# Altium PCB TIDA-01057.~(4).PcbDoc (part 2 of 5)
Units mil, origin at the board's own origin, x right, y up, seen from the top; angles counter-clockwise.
Board outline 4448 x 3930 mil, 4 copper layers (Layer 1 - Top Layer, Layer 2 - GND, Layer 3 - PWR, Layer 4 - Bottom Layer), stack 59.034 mil thick; 537 components, 284 nets, 1540 pads, 770 vias.
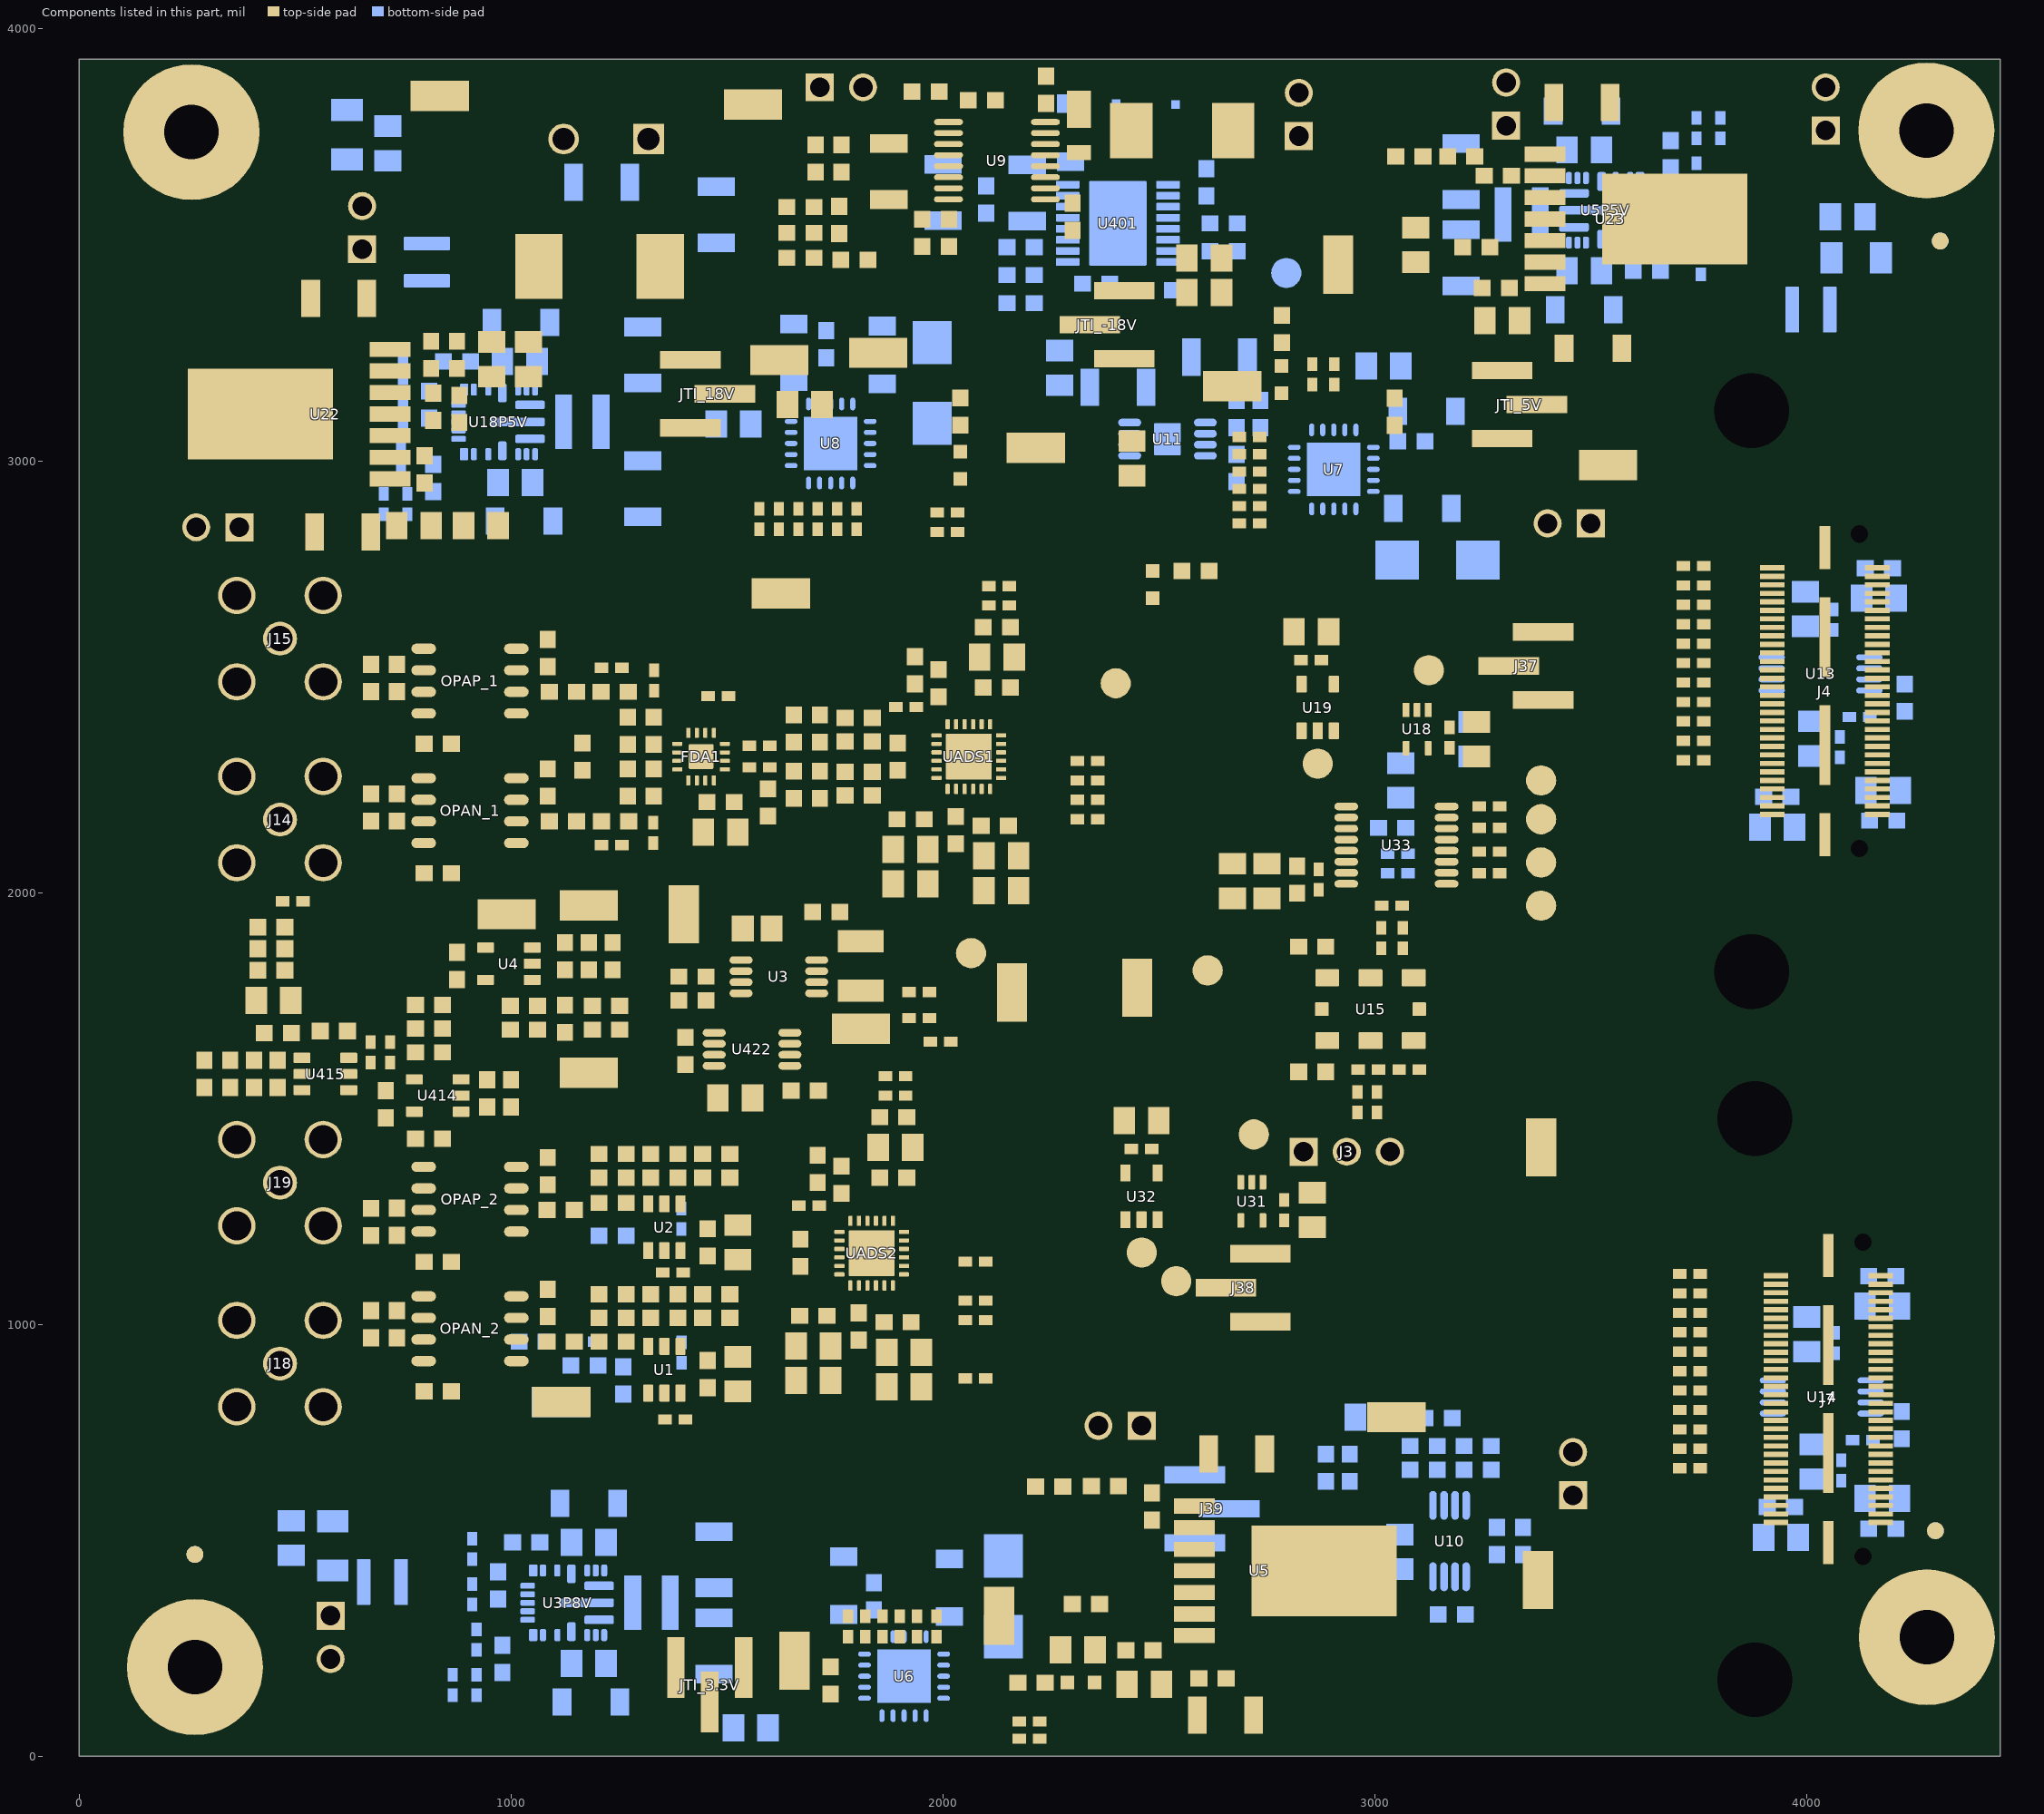
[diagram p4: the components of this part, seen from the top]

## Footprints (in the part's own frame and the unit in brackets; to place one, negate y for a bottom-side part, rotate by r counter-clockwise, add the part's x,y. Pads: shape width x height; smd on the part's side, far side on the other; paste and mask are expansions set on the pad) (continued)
DGK0008A_N [mm] "TSOP, 8-Leads, Body 3x3mm, Pitch 0.65mm, IPC Medium Density"
  oval 1.35x0.45 smd: 1(-2.225,0.975) 2(-2.225,0.325) 3(-2.225,-0.325) 4(-2.225,-0.975) 5(2.225,-0.975) 6(2.225,-0.325) 7(2.225,0.325) 8(2.225,0.975)
  silkscreen extent -2.75,-1.55 0.95,1.55, body extent -2.45,-1.5 2.45,1.5, height 0.96
DGN0008D_N [mm] "TSOP, 8-Leads, Body 3x3mm, Pitch 0.65mm, Thermal Pad 1.89x1.57mm, IPC Medium Density"
  rrect100% 1.35x0.45 smd: 1(-2.225,0.975) 2(-2.225,0.325) 3(-2.225,-0.325) 4(-2.225,-0.975) 5(2.225,-0.975) 6(2.225,-0.325) 7(2.225,0.325) 8(2.225,0.975)
  rrect6% 1.57x1.89 smd: 9(0,0)
  silkscreen extent -2.73,-1.55 0.95,1.55, body extent -2.46,-1.5 2.46,1.5, height 1.1
DR73 [mm]
  rect 2.5x3.25 smd: 1(-3,0) 2(3,0)
  silkscreen extent -4.75,-3.8 4.75,3.8, body extent -3.8,-3.8 3.8,3.8, height 3.55
Fiducial10-20 [mm]
  round 1 smd mask+0.5: 1(0,0)
Keystone_1902C [mil] "Hex Standoff, 4-40 threaded, nylon"
  body extent -145,-126 146,126, height 501
MTC16_N [mm] "TSOP, 16-Leads, Body 5x4.4mm, Pitch 0.65mm, IPC Medium Density"
  oval 1.7x0.35 smd: 1(-2.85,2.275) 2(-2.85,1.625) 3(-2.85,0.975) 4(-2.85,0.325) 5(-2.85,-0.325) 6(-2.85,-0.975) 7(-2.85,-1.625) 8(-2.85,-2.275) 9(2.85,-2.275) 10(2.85,-1.625) 11(2.85,-0.975) 12(2.85,-0.325) 13(2.85,0.325) 14(2.85,0.975) 15(2.85,1.625) 16(2.85,2.275)
  silkscreen extent -2.97,-2.55 1.6,3.12, body extent -2.25,-2.55 2.25,2.55, height 1.1
MUA08A_N [mm] "TSOP, 8-Leads, Body 3x3mm, Pitch 0.65mm, IPC Medium Density"
  oval 1.7x0.45 smd: 1(-2.1,0.975) 2(-2.1,0.325) 3(-2.1,-0.325) 4(-2.1,-0.975) 5(2.1,-0.975) 6(2.1,-0.325) 7(2.1,0.325) 8(2.1,0.975)
  silkscreen extent -2.22,-1.55 0.85,1.88, body extent -1.6,-1.6 1.6,1.6, height 1.09
Net-Tie_50milWide_30milLong [mil] "50mil net tie, no solder mask opening, no solder paste"
  rect 30x100 on Mid1 paste-20 mask-20: 1(-15,0) 2(15,0)
NR3015 [mm] "SMD, 2-Leads, Body 3x3mm"
  rrect12% 0.8x2.7 smd: 1(-1.1,0) 2(1.1,0)
  silkscreen extent -0.3,-1.6 0.3,1.6, body extent -1.5,-1.5 1.5,1.5, height 1.5
"NY PMS 440 0025 PH" [mm] "4-40 nylon screw and mounting hole"
  round 8 hole 3.2: 1(0,0)
  body extent -3.3,-3.3 3.3,3.3, height 2.69
Pb-Free_Overlay_Small [mil]
  silkscreen extent -46,-46 46,46
PogoPad [mil] "No Solder Paste"
  round 70 smd paste-35: 1(0,0)
PowerDI123 [mm] "Diodes Inc recommended land pattern, document number DS30628 Rev. 6-2"
  rect 2.2x1.4 smd: 1(-1.275,0)
  rect 0.9x1.4 smd: 2(1.275,0)
  silkscreen extent -3.1,-1.09 1.76,1.09, body extent -2.38,-0.97 1.52,0.96, height 1
PW0016A_N [mm] "TSOP, 16-Leads, Body 5x4.4mm, Pitch 0.65mm, IPC Medium Density"
  oval 1.4x0.45 smd: 1(-2.95,2.275) 2(-2.95,1.625) 3(-2.95,0.975) 4(-2.95,0.325) 5(-2.95,-0.325) 6(-2.95,-0.975) 7(-2.95,-1.625) 8(-2.95,-2.275) 9(2.95,-2.275) 10(2.95,-1.625) 11(2.95,-0.975) 12(2.95,-0.325) 13(2.95,0.325) 14(2.95,0.975) 15(2.95,1.625) 16(2.95,2.275)
  silkscreen extent -3.5,-2.55 1.85,2.75, body extent -3.21,-2.5 3.21,2.5, height 1
PWP0016G_N [mm] "TSOP, 16-Leads, Body 5x4.4mm, Pitch 0.65mm, Thermal Pad 2.41x3.29 mm, IPC Medium Density"
  rrect22% 1.4x0.45 smd: 1(-2.95,2.275) 2(-2.95,1.625) 3(-2.95,0.975) 4(-2.95,0.325) 5(-2.95,-0.325) 6(-2.95,-0.975) 7(-2.95,-1.625) 8(-2.95,-2.275) 9(2.95,-2.275) 10(2.95,-1.625) 11(2.95,-0.975) 12(2.95,-0.325) 13(2.95,0.325) 14(2.95,0.975) 15(2.95,1.625) 16(2.95,2.275)
  rrect6% 3.4x5 smd paste-1.7 mask-1.7: 17(0,0)
  rrect4% 2.41x3.29 on Bottom Paste: 17(0,0)
  rrect4% 2.41x3.29 on Bottom Solder: 17(0,0)
  silkscreen extent -3.5,-2.55 1.5,2.73, body extent -3.21,-2.5 3.21,2.5, height 0.99
RGE0024H [mm] "QFN, 24-Leads, Body 4x4mm, Pitch 0.5mm, Thermal Pad 2.7x2.7mm, TI Recommended"
  rrect40% 0.6x0.25 smd: 1(-1.9,1.25) 2(-1.9,0.75) 3(-1.9,0.25) 4(-1.9,-0.25) 5(-1.9,-0.75) 6(-1.9,-1.25) 13(1.9,-1.25) 14(1.9,-0.75) 15(1.9,-0.25) 16(1.9,0.25) 17(1.9,0.75) 18(1.9,1.25)
  rrect40% 0.25x0.6 smd: 7(-1.25,-1.9) 8(-0.75,-1.9) 9(-0.25,-1.9) 10(0.25,-1.9) 11(0.75,-1.9) 12(1.25,-1.9) 19(1.25,1.9) 20(0.75,1.9) 21(0.25,1.9) 22(-0.25,1.9) 23(-0.75,1.9) 24(-1.25,1.9)
  rrect4% 2.7x2.7 smd paste-1.35: 25(0,0)
  silkscreen extent -2.22,-2.22 2.22,2.22, body extent -2.07,-2.07 2.07,2.07, height 1.01
RGT0016A [mm] "QFN, 16-Leads, Body 3x3mm, Pitch 0.5mm, Thermal Pad 1.45x1.45mm, TI Recommended"
  rrect42% 0.6x0.24 smd: 1(-1.4,0.75) 2(-1.4,0.25) 3(-1.4,-0.25) 4(-1.4,-0.75) 9(1.4,-0.75) 10(1.4,-0.25) 11(1.4,0.25) 12(1.4,0.75)
  rrect42% 0.24x0.6 smd: 5(-0.75,-1.4) 6(-0.25,-1.4) 7(0.25,-1.4) 8(0.75,-1.4) 13(0.75,1.4) 14(0.25,1.4) 15(-0.25,1.4) 16(-0.75,1.4)
  rrect7% 1.45x1.45 smd paste-0.725: 17(0,0)
  silkscreen extent -1.72,-1.73 1.72,1.73, body extent -1.57,-1.57 1.58,1.58, height 1.01
RGW0020A [mm] "QFN, 20-Leads, Body 5x5mm, Pitch 0.65mm, Thermal Pad 3.15x3.15mm, TI Recommended"
  oval 0.75x0.3 smd: 1(-2.325,1.3) 2(-2.325,0.65) 3(-2.325,0) 4(-2.325,-0.65) 5(-2.325,-1.3) 11(2.325,-1.3) 12(2.325,-0.65) 13(2.325,0) 14(2.325,0.65) 15(2.325,1.3)
  oval 0.3x0.75 smd: 6(-1.3,-2.325) 7(-0.65,-2.325) 8(0,-2.325) 9(0.65,-2.325) 10(1.3,-2.325) 16(1.3,2.325) 17(0.65,2.325) 18(0,2.325) 19(-0.65,2.325) 20(-1.3,2.325)
  rect 3.15x3.15 smd paste-1.575: 21(0,0)
  silkscreen extent -2.73,-2.73 2.73,2.73, body extent -2.58,-2.57 2.57,2.58, height 1.01
RNL0022A_NV [mm] "VQFN, 22 pin, 0.5 mm pitch"
  rrect25% 0.7x0.5 smd paste-0.05 mask-0.05: 1(-1.9,2) 17(1.9,2)
  rrect40% 0.7x0.35 smd paste-0.05 mask-0.05: 2(-1.9,1.425) 3(-1.9,0.575) 15(1.9,0.575) 16(1.9,1.425)
  rrect40% 1.1x0.5 smd paste-0.25 mask-0.05: 4(-1.7,-0.25) 14(1.7,-0.25)
  rrect25% 0.4x0.4 on Bottom Paste: 4A(-2,-0.25) 4B(-1.4,-0.25) 14A(1.4,-0.25) 14B(2,-0.25)
  rrect57% 0.7x0.35 smd paste-0.05 mask-0.05: 5(-1.9,-1.175) 6(-1.9,-1.675) 7(-1.9,-2.175) 11(1.9,-2.175) 12(1.9,-1.675) 13(1.9,-1.175)
  rrect40% 0.5x1.74 smd paste-0.25 mask-0.05: 8(-1,-1.875) 10(1,-1.875)
  rrect25% 0.4x0.66 on Bottom Paste: 8A(-1,-1.445) 8B(-1,-2.305) 10A(1,-1.445) 10B(1,-2.305)
  rrect40% 0.5x3.25 smd paste-0.25 mask-0.05: 9(0,-1.125)
  rrect25% 0.4x0.63 on Bottom Paste: 9A(0,0.12) 9B(0,-0.71) 9C(0,-1.54) 9D(0,-2.37)
  rrect40% 0.35x0.85 smd paste-0.05 mask-0.05: 18(1,2.325) 19(0.5,2.325) 20(0,2.325) 21(-0.5,2.325) 22(-1,2.325)
  silkscreen extent -2.15,-2.65 2.15,2.65, body extent -2,-2.5 2,2.5, height 0.9
Samtec_QTH-030-01-x-D-A [mil] "Header (Shrouded), 19.7mil, 30x2, SMT"
  rect 12x57 smd mask+1: 1(-285.7,121.5) 2(-285.7,-121.5) 3(-266,121.5) 4(-266,-121.5) 5(-246.3,121.5) 6(-246.3,-121.5) 7(-226.6,121.5) 8(-226.6,-121.5) 9(-206.9,121.5) 10(-206.9,-121.5) 11(-187.2,121.5) 12(-187.2,-121.5) 13(-167.5,121.5) 14(-167.5,-121.5) 15(-147.8,121.5) 16(-147.8,-121.5) 17(-128.1,121.5) 18(-128.1,-121.5) 19(-108.4,121.5) 20(-108.4,-121.5) 21(-88.7,121.5) 22(-88.7,-121.5) 23(-69,121.5) 24(-69,-121.5) 25(-49.3,121.5) 26(-49.3,-121.5) 27(-29.6,121.5) 28(-29.6,-121.5) 29(-9.9,121.5) 30(-9.9,-121.5) 31(9.8,121.5) 32(9.8,-121.5) 33(29.5,121.5) 34(29.5,-121.5) 35(49.2,121.5) 36(49.2,-121.5) 37(68.9,121.5) 38(68.9,-121.5) 39(88.6,121.5) 40(88.6,-121.5) 41(108.3,121.5) 42(108.3,-121.5) 43(128,121.5) 44(128,-121.5) 45(147.7,121.5) 46(147.7,-121.5) 47(167.4,121.5) 48(167.4,-121.5) 49(187.1,121.5) 50(187.1,-121.5) 51(206.8,121.5) 52(206.8,-121.5) 53(226.5,121.5) 54(226.5,-121.5) 55(246.2,121.5) 56(246.2,-121.5) 57(265.9,121.5) 58(265.9,-121.5) 59(285.6,121.5) 60(285.6,-121.5)
  round 0 hole 40 unplated mask+1: MH1(-364,80) MH2(364,80)
  rect 100x25 smd mask+1: MP1(-332.7,0) MP4(332.3,0)
  rect 185x25 smd mask+1: MP2(-125.2,0) MP3(124.8,0)
  silkscreen extent -394,-118 394,131, body extent -394,-140 394,140, height 170
Samtec_TMM-103-01-x-S-SM [mm] "Header,2mm, 3x1, SMT"
  rect 1.02x3.56 smd: 1(-2,1.015) 2(0,-1.015) 3(2,1.015)
  silkscreen extent -3.2,-0.99 3,0.99, body extent -3,-2.41 3,2.41, height 5.97
SIA0008B [mm] "SIP 8-Leads, Body 5x7mm"
  rrect17% 1x0.6 on Top Paste: 1(-1.85,2.14) 1(-1.85,2.94) 2(-1.85,-0.4) 2(-1.85,0.4) 3(-1.85,-2.94) 3(-1.85,-2.14) 4(1.85,-2.94) 4(1.85,-2.14) 5(1.85,-0.4) 5(1.85,0.4) 6(1.85,2.14) 6(1.85,2.94)
  rrect10% 1x1.4 smd paste-0.5: 1(-1.85,2.54) 2(-1.85,0) 3(-1.85,-2.54) 4(1.85,-2.54) 5(1.85,0) 6(1.85,2.54)
  rrect12% 0.8x0.8 smd: 7(0,2.865) 8(0,-2.865)
  silkscreen extent -2.64,-3.63 2.64,3.63, body extent -2.56,-3.56 2.56,3.56, height 1.13
SMC [mil] "Molded Diode, 2-Leads, Body 6.9x5.8mm, IPC Medium Density, based on OnSemi component dimensions and land patterns"
  rect 110x150 smd: 1(-140.49,0) 2(140.49,0)
  silkscreen extent -221,-124 189,123, body extent -156,-116 156,116, height 91
Testpoint_Keystone_Miniature [mil] "Miniature SMT test point"
  rect 135x70 smd: 1(0,0)
  silkscreen extent -78,-46 78,45, body extent -52,-20 52,20, height 61
TI_Stacked_Overlay_Small [mil]
  silkscreen extent -418,-98 418,98
TSOP65P640X120-8N [mm] "TSOP, 8-Leads, Body 3.1x4.5mm (max), Pitch 0.65mm, IPC Medium Density"
  oval 1.55x0.35 smd mask+0.08: 1(-2.875,0.975) 2(-2.875,0.325) 3(-2.875,-0.325) 4(-2.875,-0.975) 5(2.875,-0.975) 6(2.875,-0.325) 7(2.875,0.325) 8(2.875,0.975)
  silkscreen extent -1.7,-1.55 1.7,1.55, body extent -2.25,-1.55 2.25,1.55, height 1.21
TZA07A_V [mm] "D2-PAK, 8-Leads, Body 9.9x10.2mm, Pitch 1.27mm, Lead Span 13.8mm, NSC Recommended"
  rect 2.41x0.89 smd: 1(-5.35,3.81) 2(-5.35,2.54) 3(-5.35,1.27) 4(-5.35,0) 5(-5.35,-1.27) 6(-5.35,-2.54) 7(-5.35,-3.81)
  rect 8.54x5.35 smd: 8(2.28,0)
  silkscreen extent -5.47,-5.15 -2.7,5.15, body extent -2.55,-5.2 7.55,5.2, height 4.67
WE-TPC_2828 [mm] "WURTH"
  rect 1x3.2 smd: 1(-1.1,0) 2(1.1,0)
  body extent -1.5,-1.5 1.5,1.5, height 3
WE-TPC_3816 [mm] "WERTH"
  rect 0.5x0.5 smd: 1(-1.75,0) 2(1.75,0.05)
  Layer 1 - Top Layer region: 0.55,2.15 2.15,2.15 2.15,-2.15 0.55,-2.15 0.55,-1.35 0.56,-1.173 1.015,-0.813 1.267,-0.29 1.267,0.29 1.015,0.813 0.56,1.173 0.56,1.173 0.55,1.4
  Layer 1 - Top Layer region: -0.55,-2.15 -2.15,-2.15 -2.15,2.15 -0.55,2.15 -0.55,1.35 -0.56,1.173 -1.015,0.813 -1.267,0.29 -1.267,-0.29 -1.015,-0.813 -0.56,-1.173 -0.56,-1.173 -0.55,-1.4
  silkscreen extent -0.3,-2.15 0.3,2.15, body extent -2.05,-2.05 2.05,2.05, height 1.8
WL-SMCW_RED [mm] "WURTH"
  rect 0.8x0.8 smd: 1(-0.8,0) 2(0.8,0)
  silkscreen extent -1.9,-0.8 1.2,0.8, body extent -0.85,-0.45 0.85,0.45, height 0.8
WURTH_61300211121 [mm] "Header, 2.54mm, 2x1, TH"
  rect 1.65x1.65 hole 1.15: 1(-1.27,0)
  round 1.65 hole 1.15: 2(1.27,0)
  silkscreen extent -2.54,-1.27 2.54,1.6, body extent -2.54,-1.27 2.54,1.27, height 8.54
WURTH_61300311121 [mm] "Header, 2.54mm, 3x1, TH"
  rect 1.65x1.65 hole 1.15: 1(-2.54,0)
  round 1.65 hole 1.15: 2(0,0) 3(2.54,0)
  silkscreen extent -3.81,-1.27 3.81,1.6, body extent -3.81,-1.27 3.81,1.27, height 8.54
Wurth_691213710002 [mm] "TH, 2-Leads, Body 10x8.3mm, Pitch 5mm"
  rect 1.8x1.8 hole 1.3: 1(-2.5,0)
  round 1.8 hole 1.3: 2(2.5,0)
  silkscreen extent -5,-4.75 5,4.15, body extent -5.6,-4.15 5,4.15, height 10
Wurth_WA-SMSI [mm] "ROUND STANDOFF M3 STEEL 5MM"
  round 0 hole 4.4 unplated: ""(0,0)
  Layer 1 - Top Layer region: -3.711,0 -3.666,-0.581 -3.53,-1.147 -3.307,-1.685 -3.003,-2.182 -2.624,-2.624 -2.182,-3.003 -1.685,-3.307 -1.147,-3.53 -0.581,-3.666 0,-3.711 0.581,-3.666 1.147,-3.53 1.685,-3.307 2.182,-3.003 2.624,-2.624 3.003,-2.182 3.307,-1.685 3.53,-1.147 3.666,-0.581 3.711,0 3.7,0 2.466,0 2.418,-0.481 2.278,-0.944 2.05,-1.37 1.744,-1.744 1.37,-2.05 0.944,-2.278 0.481,-2.418 0,-2.466 -0.481,-2.418 -0.944,-2.278 -1.37,-2.05 -1.744,-1.744 -2.05,-1.37 -2.278,-0.944 -2.418,-0.481 -2.466,0 -2.454,0
  Layer 1 - Top Layer region: -3.711,0 -3.666,0.581 -3.53,1.147 -3.307,1.685 -3.003,2.182 -2.624,2.624 -2.182,3.003 -1.685,3.307 -1.147,3.53 -0.581,3.666 0,3.711 0.581,3.666 1.147,3.53 1.685,3.307 2.182,3.003 2.624,2.624 3.003,2.182 3.307,1.685 3.53,1.147 3.666,0.581 3.711,0 3.7,0 2.466,0 2.418,0.481 2.278,0.944 2.05,1.37 1.744,1.744 1.37,2.05 0.944,2.278 0.481,2.418 0,2.466 -0.481,2.418 -0.944,2.278 -1.37,2.05 -1.744,1.744 -2.05,1.37 -2.278,0.944 -2.418,0.481 -2.466,0 -2.454,0
  silkscreen extent -4.1,-4.1 4.1,4.1, body extent -3,-3 3,3, height 5

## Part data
24Vin GNDin TP3 TP8 TP25 TP26 TP27 TP28 TP29 TP30 TP_3P3V TP_3P8V TP_5P5V TP_18P5V TPAGND1 TPAGND2 TPAGND3 TPAGND4 TPGND1 TPGND2 TPGND3 TPGND4 TPV4: "Test Point, Miniature, SMT", Manufacturer=Keystone, Supplier Part Number 1=36-5015TR-ND
C1 C43 C47 C354 C389 C391 C408 Cin Cin1 Cin2 Cin3 Cout2: "CAP, CERM, 10 兪F, 50 V, +/- 10%, X7R, 1210", Cap_Case=1210, Manufacturer="Taiyo Yuden", Supplier Part Number 1=587-3167-1-ND, TempCo=X7R, Tolerance_%=10, Value1=Unknown, Value2=50V, ValueDisplayed=10兪F
C3: "CAP, CERM, 10uF, 10V, +/-10%, X7R, 0805", Cap_Case=0805, Manufacturer=MuRata, Supplier Part Number 1=490-3905-1-ND, TempCo=X7R, Tolerance_%=10, Value1="0.003 ohm", Value2=10V, ValueDisplayed=10兪F
C4: "CAP, CERM, 1uF, 10V, +/-10%, X7R, 0603", Cap_Case=0603, Manufacturer=MuRata, Supplier Part Number 1=490-3899-1-ND, TempCo=X7R, Tolerance_%=10, Value1="0.011 ohm", Value2=10V, ValueDisplayed=1兪F
C5: "CAP, CERM, 47 兪F, 10 V, +/- 10%, X7R, 1210", Cap_Case=1210, Manufacturer=MuRata, Supplier Part Number 1=490-5312-1-ND, TempCo=X7R, Tolerance_%=10, Value1=Unknown, Value2=10V, ValueDisplayed=47兪F
C9 C12 C13 C16 C17 C20 Cout4: "CAP, CERM, 47 兪F, 25 V, +/- 20%, X5R, 1206_190", Cap_Case=1206, Manufacturer=TDK, Supplier Part Number 1=445-8047-1-ND, TempCo=X5R, Tolerance_%=20, Value1=Unknown, Value2=25V, ValueDisplayed=47兪F
C10: "CAP, CERM, 1000 pF, 100 V, +/- 10%, X7R, AEC-Q200 Grade 1, 0603", Cap_Case=0603, Manufacturer=TDK, Supplier Part Number 1=445-5806-1-ND, TempCo=X7R, Tolerance_%=10, Value1="1.97137 ohm", Value2=100V, ValueDisplayed=1000pF
C11 C42 C45 Cout3: "CAP, CERM, 1 兪F, 100 V, +/- 10%, X7S, 0805", Cap_Case=0805, Manufacturer=TDK, Supplier Part Number 1=445-5205-1-ND, TempCo=X7S, Tolerance_%=10, Value1="0.008255 ohm", Value2=100V, ValueDisplayed=1兪F
C14 C18: "CAP, CERM, 1000 pF, 50 V, +/- 1%, C0G/NP0, 0603", Cap_Case=0603, Manufacturer=MuRata, Supplier Part Number 1=490-6377-1-ND, TempCo=C0G/NP0, Tolerance_%=1, Value1=Unknown, Value2=50V, ValueDisplayed=1000pF
C15 C19 C318 C319 C321 C339 C348 C453 CR479: "CAP, CERM, 1 兪F, 25 V, +/- 10%, X7R, 0603", Cap_Case=0603, Manufacturer=MuRata, Supplier Part Number 1=490-5307-1-ND, TempCo=X7R, Tolerance_%=10, Value1=Unknown, Value2=25V, ValueDisplayed=1兪F
C21 C22 C57 C58 C59 C60 C261 C262 C271 C272 C284 C287 C288 C289 C290 C291 C304 C305 C306 C307 C308 C338 C343 C345 C347 CR481: "CAP, CERM, 10 兪F, 10 V, +/- 10%, X7R, 0805", Cap_Case=0805, Manufacturer=MuRata, Supplier Part Number 1=490-3905-1-ND, TempCo=X7R, Tolerance_%=10, Value1="0.003 ohm", Value2=10V, ValueDisplayed=10兪F
C23 C24 C33: "CAP, CERM, 10 兪F, 10 V, +/- 20%, X5R, 0603", Cap_Case=0603, Manufacturer=MuRata, TempCo=X5R, Tolerance_%=20, Value1=Unknown, Value2=10V, ValueDisplayed=10兪F
C25: "CAP, CERM, 0.47 兪F, 25 V, +/- 10%, X7R, 0603", Cap_Case=0603, Manufacturer=MuRata, Supplier Part Number 1=490-3291-1-ND, TempCo=X7R, Tolerance_%=10, Value1=Unknown, Value2=25V, ValueDisplayed=0.47兪F
C26 C28: "CAP, CERM, 22 兪F, 6.3 V, +/- 20%, X5R, 0603", Cap_Case=0603, Manufacturer=MuRata, Supplier Part Number 1=490-7611-1-ND, TempCo=X5R, Tolerance_%=20, Value1=Unknown, Value2=6.3V, ValueDisplayed=22兪F
C27: "CAP, CERM, 0.1 兪F, 16 V, +/- 10%, X5R, 0603", Cap_Case=0603, Manufacturer=MuRata, Supplier Part Number 1=GRM188R61C104KA01D-ND, TempCo=X5R, Tolerance_%=10, Value1=Unknown, Value2=16V, ValueDisplayed=0.1兪F
C29: "CAP, CERM, 4.7 兪F, 10 V, +/- 20%, X5R, 0603", Cap_Case=0603, Manufacturer=MuRata, TempCo=X5R, Tolerance_%=20, Value1=Unknown, Value2=10V, ValueDisplayed=4.7兪F
C30: "CAP, CERM, 0.22 兪F, 10 V, +/- 10%, X5R, 0603", Cap_Case=0603, Manufacturer=MuRata, Supplier Part Number 1=490-1537-1-ND, TempCo=X5R, Tolerance_%=10, Value1=Unknown, Value2=10V, ValueDisplayed=0.22兪F
C31: "CAP, CERM, 0.22 兪F, 50 V, +/- 10%, X7R, AEC-Q200 Grade 1, 0603", Cap_Case=0603, Manufacturer=MuRata, Supplier Part Number 1=490-5402-1-ND, TempCo=X7R, Tolerance_%=10, Value1=Unknown, Value2=50V, ValueDisplayed=0.22兪F
C32 C35: "CAP, CERM, 0.1 兪F, 50 V, +/- 10%, X7R, 0603", Cap_Case=0603, Manufacturer=TDK, Supplier Part Number 1=445-1314-1-ND, TempCo=X7R, Tolerance_%=10, Value1="0.0296 ohm", Value2=50V, ValueDisplayed=0.1兪F
C34: "CAP, CERM, 0.033 兪F, 50 V, +/- 10%, X7R, 0603", Cap_Case=0603, Manufacturer=MuRata, Supplier Part Number 1=490-3286-1-ND, TempCo=X7R, Tolerance_%=10, Value1=Unknown, Value2=50V, ValueDisplayed=0.033兪F
C37: "CAP, CERM, 910 pF, 50 V, +/- 5%, C0G/NP0, 0603", Cap_Case=0603, Manufacturer=Kemet, Supplier Part Number 1=399-3292-1-ND, TempCo=C0G/NP0, Tolerance_%=5, Value1=Unknown, Value2=50V, ValueDisplayed=910pF
C38: "CAP, CERM, 10 pF, 50 V, +/- 5%, C0G/NP0, AEC-Q200 Grade 1, 0603", Cap_Case=0603, Manufacturer=TDK, Supplier Part Number 1=445-5628-1-ND, TempCo=C0G/NP0, Tolerance_%=5, Value1=Unknown, Value2=50V, ValueDisplayed=10pF
C39: "CAP, CERM, 150 pF, 50 V, +/- 5%, C0G/NP0, 0603", Cap_Case=0603, Manufacturer=MuRata, Supplier Part Number 1=490-1431-1-ND, TempCo=C0G/NP0, Tolerance_%=5, Value1=Unknown, Value2=50V, ValueDisplayed=150pF
C40: "CAP, CERM, 0.022 兪F, 50 V, +/- 10%, X7R, 0603", Cap_Case=0603, Manufacturer=MuRata, Supplier Part Number 1=490-1517-1-ND, TempCo=X7R, Tolerance_%=10, Value1=Unknown, Value2=50V, ValueDisplayed=0.022兪F
C41: "CAP, CERM, 22 兪F, 35 V, +/- 20%, X5R, 0805", Cap_Case=0805, Manufacturer=TDK, Supplier Part Number 1=445-14428-1-ND, TempCo=X5R, Tolerance_%=20, Value1="0.00205 ohm", Value2=35V, ValueDisplayed=22兪F
C46: "CAP, CERM, 0.01 兪F, 50 V, +/- 10%, X7R, AEC-Q200 Grade 1, 0603", Cap_Case=0603, Manufacturer=MuRata, Supplier Part Number 1=490-4778-1-ND, TempCo=X7R, Tolerance_%=10, Value1=Unknown, Value2=50V, ValueDisplayed=0.01兪F
C53 C54 C55 C56 C94 C95 C340 C344 C346 C349 C350: "CAP, CERM, 0.1 兪F, 16 V, +/- 10%, X7R, 0402", Cap_Case=0402, Manufacturer=MuRata, Supplier Part Number 1=490-3261-1-ND, TempCo=X7R, Tolerance_%=10, Value1=Unknown, Value2=16V, ValueDisplayed=0.1兪F
C61 C84 C85 C91 C92 C93 C108 C112 C116 C120 C121 C122 C259 C260 C266 C267 C268 C269 C320 C454 C455 C460: "CAP, CERM, 0.1 兪F, 25 V, +/- 5%, X7R, 0603", Cap_Case=0603, Manufacturer=Kemet, Supplier Part Number 1=399-1282-1-ND, TempCo=X7R, Tolerance_%=5, Value1=Unknown, Value2=25V, ValueDisplayed=0.1兪F
C62 C449 C457 C458 C459: "CAP, CERM, 10 兪F, 10 V, +/- 10%, X7T, 0603", Cap_Case=0603, Manufacturer=MuRata, Supplier Part Number 1=490-10987-1-ND, TempCo=X7T, Tolerance_%=10, Value1=Unknown, Value2=10V, ValueDisplayed=10兪F
C63 C64: "CAP, CERM, 0.1 兪F, 25 V, +/- 10%, X5R, 0402", Cap_Case=0402, Manufacturer=MuRata, Supplier Part Number 1=490-5920-1-ND, TempCo=X5R, Tolerance_%=10, Value1=Unknown, Value2=25V, ValueDisplayed=0.1兪F
C71 C72 C96 C97: "CAP, CERM, 100 pF, 100 V, +/- 5%, C0G/NP0, AEC-Q200 Grade 1, 0603", Cap_Case=0603, Manufacturer=MuRata, Supplier Part Number 1=490-4771-1-ND, TempCo=C0G/NP0, Tolerance_%=5, Value1=Unknown, Value2=100V, ValueDisplayed=100pF
C79 C80 C81 C82 C104 C105 C106 C107: "CAP, CERM, 0.1 兪F, 100 V, +/- 10%, X7R, 0603", Cap_Case=0603, Manufacturer=MuRata, Supplier Part Number 1=490-3285-1-ND, TempCo=X7R, Tolerance_%=10, Value1=Unknown, Value2=100V, ValueDisplayed=0.1兪F
C83 CMFB: "CAP, CERM, 68 pF, 100 V, +/- 5%, C0G/NP0, 0603", Cap_Case=0603, Manufacturer=MuRata, Supplier Part Number 1=490-1347-1-ND, TempCo=C0G/NP0, Tolerance_%=5, Value1=Unknown, Value2=100V, ValueDisplayed=68pF
C86 C87 C111 C114: "CAP, CERM, 390 pF, 100 V, +/- 5%, C0G/NP0, 0603", Cap_Case=0603, Manufacturer=MuRata, Supplier Part Number 1=490-1365-1-ND, TempCo=C0G/NP0, Tolerance_%=5, Value1=Unknown, Value2=100V, ValueDisplayed=390pF
C88 C119: "CAP, CERM, 1 兪F, 10 V, +/- 10%, X7R, 0603", Cap_Case=0603, Manufacturer=MuRata, Supplier Part Number 1=490-3899-1-ND, TempCo=X7R, Tolerance_%=10, Value1="0.011 ohm", Value2=10V, ValueDisplayed=1兪F
C89 C90 C117 C118 C315 C316 C317: "CAP, CERM, 1000 pF, 100 V, +/- 5%, C0G/NP0, 0603", Cap_Case=0603, Manufacturer=TDK, Supplier Part Number 1=445-2312-1-ND, TempCo=C0G/NP0, Tolerance_%=5, Value1="0.0589 ohm", Value2=100V, ValueDisplayed=1000pF
C109 C115: "CAP, CERM, 1000 pF, 50 V, +/- 5%, C0G/NP0, 0603", Cap_Case=0603, Manufacturer=Kemet, Supplier Part Number 1=317202, TempCo=C0G/NP0, Tolerance_%=5, Value1=Unknown, Value2=50V, ValueDisplayed=1000pF
C110 C113: "CAP, CERM, 130 pF, 100 V, +/- 5%, C0G/NP0, 0603", Cap_Case=0603, Manufacturer=MuRata, Supplier Part Number 1=490-1354-1-ND, TempCo=C0G/NP0, Tolerance_%=5, Value1=Unknown, Value2=100V, ValueDisplayed=130pF
C322 C323: "CAP, CERM, 22 兪F, 10 V, +/- 20%, X5R, 0603", Cap_Case=0603, Manufacturer=TDK, Supplier Part Number 1=445-9077-1-ND, TempCo=X5R, Tolerance_%=20, Value1="0.00371 ohm", Value2=10V, ValueDisplayed=22兪F
C335: "CAP, CERM, 0.01 兪F, 50 V, +/- 5%, C0G/NP0, AEC-Q200 Grade 1, 0603", Cap_Case=0603, Manufacturer=TDK, Supplier Part Number 1=445-6916-1-ND, TempCo=C0G/NP0, Tolerance_%=5, Value1=Unknown, Value2=50V, ValueDisplayed=0.01兪F
C351 C352 C353: "CAP, TA, 4.7 兪F, 25 V, +/- 10%, 2 ohm, SMD", Cap_Case=C, Manufacturer=Vishay-Sprague, Supplier Part Number 1=718-1082-1-ND, Tolerance_%=10, Value1="2 ohm", Value2=25V, ValueDisplayed=4.7兪F
C355 C359 C360 C367 C371 C372 C379 C383 C384: "CAP, CERM, 0.1 兪F, 100 V, +/- 10%, X7R, 0805", Cap_Case=0805, Manufacturer=TDK, Supplier Part Number 1=445-1418-1-ND, TempCo=X7R, Tolerance_%=10, Value1="0.020726 ohm", Value2=100V, ValueDisplayed=0.1兪F
C356 C368 C380: "CAP, CERM, 4.7 兪F, 35 V, +/- 10%, X7R, 1206", Cap_Case=1206, Manufacturer=TDK, Supplier Part Number 1=445-14805-1-ND, TempCo=X7R, Tolerance_%=10, Value1="0.003785 ohm", Value2=35V, ValueDisplayed=4.7兪F
C357 C358 C369 C370 C381 C382: "CAP, CERM, 10 兪F, 25 V, +/- 10%, X7R, 1206", Cap_Case=2220, Manufacturer=MuRata, Supplier Part Number 1=81-GRM31CR71E106KA12, TempCo=X7R, Tolerance_%=10, Value1=Unknown, Value2=25V, ValueDisplayed=10兪F
C361 C373 C385: "CAP, CERM, 0.47 兪F, 25 V, +/- 10%, X7R, AEC-Q200 Grade 1, 0603", Cap_Case=0603, Manufacturer=MuRata, Supplier Part Number 1=490-4776-1-ND, TempCo=X7R, Tolerance_%=10, Value1=Unknown, Value2=25V, ValueDisplayed=0.47兪F
C362 C375 C388: "CAP, CERM, 0.1 兪F, 50 V, +/- 10%, X6S, 0402", Cap_Case=0402, Manufacturer=TDK, Supplier Part Number 1=445-7356-1-ND, TempCo=X6S, Tolerance_%=10, Value1="0.039064 ohm", Value2=50V, ValueDisplayed=0.1兪F
C363 C374 C387: "CAP, CERM, 100 pF, 25 V, +/- 5%, C0G/NP0, 0402", Cap_Case=0402, Manufacturer=Kemet, Supplier Part Number 1=399-1022-1-ND, TempCo=C0G/NP0, Tolerance_%=5, Value1=Unknown, Value2=25V, ValueDisplayed=100pF
C364 C366 C376 C378: "CAP, CERM, 22 兪F, 16 V, +/- 20%, X7R, AEC-Q200 Grade 1, 1210", Cap_Case=1210_280, Manufacturer=TDK, Supplier Part Number 1=445-5723-1-ND, TempCo=X7R, Tolerance_%=20, Value1="0.002582 ohm", Value2=16V, ValueDisplayed=22兪F
C401: "CAP, CERM, 10 兪F, 50 V, +/- 10%, X7S, 1210", Cap_Case=1210_280, Manufacturer=TDK, Supplier Part Number 1=445-4536-1-ND, TempCo=X7S, Tolerance_%=10, Value1="0.002827 ohm", Value2=50V, ValueDisplayed=10兪F
C402: "CAP, CERM, 0.1 兪F, 50 V, +/- 10%, X5R, 0603", Cap_Case=0603, Manufacturer=TDK, Supplier Part Number 1=445-7456-1-ND, TempCo=X5R, Tolerance_%=10, Value1="0.0296 ohm", Value2=50V, ValueDisplayed=0.1兪F
C403: "CAP, CERM, 4.7 兪F, 25 V, +/- 10%, X5R, 0603", Cap_Case=0603, Manufacturer=MuRata, Supplier Part Number 1=490-7203-1-ND, TempCo=X5R, Tolerance_%=10, Value1=Unknown, Value2=25V, ValueDisplayed=4.7兪F
C404: "CAP, CERM, 0.47 兪F, 50 V, +/- 10%, X5R, 0603", Cap_Case=0603, Manufacturer=TDK, Supplier Part Number 1=445-7464-1-ND, TempCo=X5R, Tolerance_%=10, Value1="0.010974 ohm", Value2=50V, ValueDisplayed=0.47兪F
C405: "CAP, CERM, 1 兪F, 35 V, +/- 10%, X7R, 0603", Cap_Case=0603, Manufacturer=TDK, Supplier Part Number 1=445-7414-1-ND, TempCo=X7R, Tolerance_%=10, Value1=Unknown, Value2=35V, ValueDisplayed=1兪F
C406: "CAP, CERM, 22 兪F, 35 V, +/- 20%, X5R, 1206", Cap_Case=1206_180, Manufacturer=TDK, Supplier Part Number 1=445-8045-1-ND, TempCo=X5R, Tolerance_%=20, Value1="0.002398 ohm", Value2=35V, ValueDisplayed=22兪F
C407: "CAP, CERM, 0.022 兪F, 25 V, +/- 10%, X7R, 0603", Cap_Case=0603, Manufacturer=Kemet, Supplier Part Number 1=399-1094-1-ND, TempCo=X7R, Tolerance_%=10, Value1=Unknown, Value2=25V, ValueDisplayed=0.022兪F
C409: "CAP, CERM, 100 pF, 50 V, +/- 5%, C0G/NP0, 0603", Cap_Case=0603, Manufacturer="Wurth Elektronik", TempCo=C0G/NP0, Tolerance_%=5, Value1=Unknown, Value2=50V, ValueDisplayed=100pF
C452: "CAP, CERM, 0.22 兪F, 16 V, +/- 5%, X7R, 0805", Cap_Case=0805, Manufacturer=AVX, Supplier Part Number 1=478-3773-1-ND, TempCo=X7R, Tolerance_%=5, Value1="0.016 ohm", Value2=16V, ValueDisplayed=0.22兪F
C461: "CAP, CERM, 10 pF, 50 V, +/- 1%, C0G/NP0, 0603", Cap_Case=0603, Manufacturer=Kemet, Supplier Part Number 1=399-9958-1-ND, TempCo=C0G/NP0, Tolerance_%=1, Value1=Unknown, Value2=50V, ValueDisplayed=10pF
Cff: "CAP, CERM, 0.022 兪F, 100 V, +/- 10%, X7R, 0603", Cap_Case=0603, Manufacturer=TDK, Supplier Part Number 1=445-2275-1-ND, TempCo=X7R, Tolerance_%=10, Value1="0.037 ohm", Value2=100V, ValueDisplayed=0.022兪F
Cff2 Cff3: "CAP, CERM, 0.022uF, 50V, +/-10%, X7R, 0805", Cap_Case=0805, Manufacturer=AVX, Supplier Part Number 1=478-1387-1-ND, TempCo=X7R, Tolerance_%=10, Value1="0.052 ohm", Value2=50V, ValueDisplayed=0.022兪F
Cout1: "CAP, CERM, 22 兪F, 35 V, +/- 20%, JB, 0805", Cap_Case=0805, Manufacturer=TDK, Supplier Part Number 1=445-11527-6-ND, TempCo=JB, Tolerance_%=20, Value1=Unknown, Value2=35V, ValueDisplayed=22兪F
Cout5: "CAP, CERM, 100 兪F, 6.3 V, +/- 20%, X6S, 1210", Cap_Case=1210_280, Manufacturer=TDK, Supplier Part Number 1=445-6016-1-ND, TempCo=X6S, Tolerance_%=20, Value1="0.005496 ohm", Value2=6.3V, ValueDisplayed=100兪F
Cout6: "CAP, CERM, 1 兪F, 25 V, +/- 10%, X7R, 0603", Cap_Case=0603, Manufacturer=Kemet, Supplier Part Number 1=399-7376-1-ND, TempCo=X7R, Tolerance_%=10, Value1=Unknown, Value2=25V, ValueDisplayed=1兪F
Css: "CAP, CERM, 4700 pF, 100 V, +/- 10%, X7R, AEC-Q200 Grade 1, 0603", Cap_Case=0603, Manufacturer=TDK, Supplier Part Number 1=445-5810-1-ND, TempCo=X7R, Tolerance_%=10, Value1="0.469862 ohm", Value2=100V, ValueDisplayed=4700pF
Css2 Css3: "CAP, CERM, 0.01 兪F, 6.3 V, +/- 10%, X7R, 0603", Cap_Case=0603, Manufacturer=MuRata, Supplier Part Number 1=GRM188R70J103KA01D-ND, TempCo=X7R, Tolerance_%=10, Value1=Unknown, Value2=6.3V, ValueDisplayed=0.01兪F
CVCC3V CVCC5V CVCC18V: "CAP, CERM, 2.2 兪F, 6.3 V, +/- 10%, X7R, AEC-Q200 Grade 1, 0603", Cap_Case=0603, Manufacturer=MuRata, Supplier Part Number 1=490-5316-1-ND, TempCo=X7R, Tolerance_%=10, Value1=Unknown, Value2=6.3V, ValueDisplayed=2.2兪F
D1: "Diode, Schottky, 200 V, 4 A, SMC", Manufacturer="ON Semiconductor", Supplier Part Number 1=MBRS4201T3GOSCT-ND, Value1=4A, Value2=0.86V
D2: "Diode, Schottky, 100 V, 1 A, PowerDI123", Manufacturer="Diodes Inc.", Supplier Part Number 1=DFLS1100DICT-ND, Value1=1A, Value2=0.77V
D14 D18 D21 D22: "LED, Red, SMD", Color=Red, Manufacturer="Wurth Elektronik", Power_TotalModule=0.072, Supplier Part Number 1=732-4978-1-ND, Value1=0.072W, Value2=2V
FDA1: library part CMP-0077753-1, "Low-Power, High Supply Range, 70-MHz, Fully Differential Amplifier, RGT0016C (VQFN-16)", Alternate Manufacturer="Texas Instruments"
FID1 FID2 FID3 FID4 FID5 FID6: "Fiducial mark.  There is nothing to buy or mount.", Manufacturer=N/A
H1 H2 H3 H4: "Machine Screw, Round, #4-40 x 1/4, Nylon, Philips panhead", DigiKeyPartNumber=H542-ND, Manufacturer="B&F Fastener Supply"
H5 H6 H7 H8: "Standoff, Hex, 0.5\"L #4-40 Nylon", Alternate Manufacturer=-, Manufacturer=Keystone, Supplier Part Number 1=1902CK-ND
H9 H11 H13 H15: "ROUND STANDOFF M3 STEEL 5MM", Manufacturer="Wurth Elektronik", Supplier Part Number 1=732-5272-1-ND
J3: "Header, 2.54 mm, 3x1, Gold, TH", Manufacturer="Wurth Elektronik eiSos", Supplier Part Number 1=732-5316-ND
J4 J7: "Header(Shrouded), 19.7mil, 30x2, Gold, SMT", Manufacturer=Samtec, Supplier Part Number 1=SAM8185-ND
J5 J6: "Header, 2.54 mm, 2x1, Gold, TH", Manufacturer="Wurth Elektronik eiSos", Supplier Part Number 1=732-5315-ND
J8: "Terminal Block, 2x1, Brass, TH", Color=Green, Manufacturer="Wurth Elektronik", Supplier Part Number 1=732-2038-ND
J14 J15 J18 J19: "SMA Straight Jack, Gold, 50 Ohm, TH", Manufacturer="Amphenol RF", Supplier Part Number 1=ARFX1231-ND
J37 J38 J39 JTI_3.3V JTI_5V JTI_18V JTI_-18V: "Header, 2mm, 3x1, Gold, SMT", Color=Black, Current_A=3.2, Manufacturer=Samtec, Supplier Part Number 1=SAM1168-03-ND, Voltage_V=500
JMTI_-18V JPRI_-18V JSI_3.3V JSI_5V JSI_18V JZI_3.3V JZI_5V JZI_18V: "Header, 2.54 mm, 2x1, Gold, TH", Manufacturer="Wurth Elektronik", Supplier Part Number 1=732-5315-ND
L1: "Inductor, Shielded Drum Core, Ferrite, 330 兪H, 0.42 A, 1.59 ohm, SMD", Manufacturer=Coiltronics, Supplier Part Number 1=513-1817-1-ND, Value1="1.59 ohm", Value2=0.42A, ValueDisplayed=330兪H
L4 L5 L6 L7 L8 L9 L10 L12 L16 L17 L18 L19: "Ferrite Bead, 600 ohm @ 100MHz, 2A, 0805", Manufacturer=TDK, Supplier Part Number 1=445-2206-1-ND, Value1="0.1 ohm", Value2=2A
L20 L22 L24: "Inductor, Wirewound, Ferrite, 3.3 兪H, 1.21 A, 0.096 ohm, AEC-Q200 Grade 2, SMD", Manufacturer="Taiyo Yuden", Supplier Part Number 1=587-2619-1-ND, Value1="0.096 ohm", Value2=1.21A, ValueDisplayed=3.3兪H
L21 L23 L25: "Inductor, Shielded Drum Core, Ferrite, 6.8 兪H, 1.1 A, 0.142 ohm, SMD", Manufacturer="Wurth Elektronik", Supplier Part Number 1=732-2616-1-ND, Value1="0.142 ohm", Value2=1.1A, ValueDisplayed=6.8兪H
L401: "Inductor, Shielded Drum Core, Metal Composite, 68 兪H, 0.22 A, 1.15 ohm, SMD", Manufacturer="Wurth Elektronik", Supplier Part Number 1=732-3652-1-ND, Value1="1.15 ohm", Value2=0.22A, ValueDisplayed=68兪H
Logo1: library part TI_Logo, "Texas Instrument Corporate Signature"
Logo2: library part Pb-Free
NT1 NT2: "Single point connection between nets."
OPAN_1 OPAN_2 OPAP_1 OPAP_2: "Low-Noise, High-Precision, JFET-Input OPERATIONAL AMPLIFIER, D0008A", Alternate Manufacturer="Texas Instruments", Alternate PartNumber=OPA827AID
R3 R4: "RES, 0.22 ohm, 1%, 0.1W, 0603", Manufacturer=Panasonic, Power_W=0.1, Supplier Part Number 1=P.22AJCT-ND, TempCo="300 ppm/C", Tolerance_%=1, Value1=1%, Value2=0.1W, Value_Code=R220
R8 R9 R10 R11 R12 R13 R14 R15 R17 R18 R19 R20 R24 R25 R26 R27 R29 R30 R31 R32 R33 R34 R35 R36 R56 R65 R66 R67 R68 R69 R70 R71 R72 R73 R74 R75 R76 R77 R78 R79 R80 R81 R82 R83 R84 R85 R86 R211 R212 R213 R223 R225 R226 R232 R233 R234 R235 R240 R248 R250 R252 R255 R259 R260 R262 R263 R279 R280 R284 R288 R453 R454 R457 RB3 RB5 RB18 REN0 REN1 RMFBN RMFBN2 RMFBP RMFBP2 RR457: "RES, 0, 5%, 0.063 W, 0402", Manufacturer=Panasonic, Power_W=0.063, Supplier Part Number 1=P0.0JCT-ND, TempCo="600 ppm/C", Tolerance_%=5, Value1=5%, Value2=0.063W, Value_Code=0000, ValueDisplayed=0
R21: "RES, 0, 5%, 0.1 W, 0603", Manufacturer=Vishay-Dale, Power_W=0.1, Supplier Part Number 1=541-0.0GCT-ND, TempCo="200 ppm/C", Tolerance_%=5, Value1=5%, Value2=0.1W, Value_Code=0000, ValueDisplayed=0
R22: "RES, 4.70, 0.5%, 0.1 W, 0603", Manufacturer="Yageo America", Power_W=0.1, TempCo="50 ppm/C", Tolerance_%=0.5, Value1=0.5%, Value2=0.1W, Value_Code=4R70, ValueDisplayed=4.70
R40: "RES, 215 k, 0.1%, 0.1 W, 0603", Manufacturer="Yageo America", Power_W=0.1, TempCo="25 ppm/C", Value1=0.1%, Value2=0.1W, Value_Code=215k
R41: "RES, 23.2 k, 0.1%, 0.1 W, 0603", Manufacturer="Susumu Co Ltd", Power_W=0.1, Supplier Part Number 1=RG16P23.2KBCT-ND, TempCo="25 ppm/C", Value1=0.1%, Value2=0.1W, Value_Code=23k2, ValueDisplayed=23.2k
R42: "RES, 1.65 k, 0.1%, 0.1 W, 0603", Manufacturer="Susumu Co Ltd", Power_W=0.1, Supplier Part Number 1=RG16P1.65KBCT-ND, TempCo="25 ppm/C", Value1=0.1%, Value2=0.1W, Value_Code=1k65, ValueDisplayed=1.65k
R43: "RES, 30.9 k, 0.1%, 0.1 W, 0603", Manufacturer="Susumu Co Ltd", Power_W=0.1, Supplier Part Number 1=RG16P30.9KBCT-ND, TempCo="25 ppm/C", Value1=0.1%, Value2=0.1W, Value_Code=30k9, ValueDisplayed=30.9k
R44: "RES, 2.15 k, 0.1%, 0.1 W, 0603", Manufacturer="Yageo America", Power_W=0.1, TempCo="25 ppm/C", Value1=0.1%, Value2=0.1W, Value_Code=2k15, ValueDisplayed=2.15k
R45: "RES, 52.3 k, 0.1%, 0.1 W, 0603", Manufacturer="Yageo America", Power_W=0.1, TempCo="25 ppm/C", Value1=0.1%, Value2=0.1W, Value_Code=52k3, ValueDisplayed=52.3k
R46: "RES, 910, 5%, 0.1 W, 0603", Manufacturer="Yageo America", Power_W=0.1, Supplier Part Number 1=311-910GRCT-ND, TempCo="100 ppm/C", Tolerance_%=5, Value1=5%, Value2=0.1W, Value_Code=910R, ValueDisplayed=910
R47: "RES, 18.0 k, 0.1%, 0.1 W, 0603", Manufacturer="Yageo America", Power_W=0.1, TempCo="25 ppm/C", Value1=0.1%, Value2=0.1W, Value_Code=18k0, ValueDisplayed=18.0k
R50 R216: "RES, 20.0 k, 0.1%, 0.1 W, 0603", Manufacturer="Susumu Co Ltd", Power_W=0.1, Supplier Part Number 1=RG16P20.0KBCT-ND, TempCo="25 ppm/C", Value1=0.1%, Value2=0.1W, Value_Code=20k0, ValueDisplayed=20.0k
R64 R87: "RES, 10.0 k, 1%, 0.1 W, 0603", Manufacturer=Vishay-Dale, Power_W=0.1, Supplier Part Number 1=541-10.0KHCT-ND, TempCo="100 ppm/C", Tolerance_%=1, Value1=1%, Value2=0.1W, Value_Code=10k0, ValueDisplayed=10.0k
R88 R89 R90 R91: "RES, 4.7 k, 5%, 0.063 W, 0402", Manufacturer=Vishay-Dale, Power_W=0.063, Supplier Part Number 1=541-4.7KJCT-ND, TempCo="200 ppm/C", Tolerance_%=5, Value1=5%, Value2=0.063W, Value_Code=4k70, ValueDisplayed=4.7k
R92: "RES, 100, 5%, 0.063 W, 0402", Manufacturer=Vishay-Dale, Power_W=0.063, Supplier Part Number 1=541-100JCT-ND, TempCo="200 ppm/C", Tolerance_%=5, Value1=5%, Value2=0.063W, Value_Code=100R, ValueDisplayed=100
R95 R256 R257 R278: "RES, 33, 5%, 0.063 W, 0402", Manufacturer=Vishay-Dale, Power_W=0.063, Supplier Part Number 1=541-33JCT-ND, TempCo="200 ppm/C", Tolerance_%=5, Value1=5%, Value2=0.063W, Value_Code=33R0, ValueDisplayed=33
R97 R98 R107 R108 R110 R214 R485 R491: "RES, 1.00 k, 0.1%, 0.1 W, 0603", Manufacturer="Susumu Co Ltd", Power_W=0.1, Supplier Part Number 1=RG16P1.0KBCT-ND, TempCo="25 ppm/C", Value1=0.1%, Value2=0.1W, Value_Code=1k00, ValueDisplayed=1.00k
R99: "RES, 249, 1%, 0.1 W, 0603", Manufacturer=Vishay-Dale, Power_W=0.1, Supplier Part Number 1=541-249HCT-ND, TempCo="100 ppm/C", Tolerance_%=1, Value1=1%, Value2=0.1W, Value_Code=249R, ValueDisplayed=249
R100 R101 R114 R116 RDN2 RDN4 RDP2 RDP4: "RES, 1.00 k, 0.1%, 0.1 W, 0603", Manufacturer="Yageo America", Power_W=0.1, Supplier Part Number 1=YAG2179CT-ND, TempCo="10 ppm/C", Value1=0.1%, Value2=0.1W, Value_Code=1k00, ValueDisplayed=1.00k
R103 R104 R115 R117: "RES, 20.0, 0.1%, 0.1 W, 0603", Manufacturer="Yageo America", Power_W=0.1, TempCo="25 ppm/C", Value1=0.1%, Value2=0.1W, Value_Code=20R0, ValueDisplayed=20.0
R112 R113: "RES, 124, 1%, 0.1 W, 0603", Manufacturer="Yageo America", Power_W=0.1, Supplier Part Number 1=311-124HRCT-ND, TempCo="200 ppm/C", Tolerance_%=1, Value1=1%, Value2=0.1W, Value_Code=124R, ValueDisplayed=124
R215 R492: "RES, 499, 0.1%, 0.1 W, 0603", Manufacturer="Susumu Co Ltd", Power_W=0.1, Supplier Part Number 1=RG16P499BCT-ND, TempCo="25 ppm/C", Value1=0.1%, Value2=0.1W, Value_Code=499R, ValueDisplayed=499
R217 R218 R246 R247: "RES, 49.9 k, 0.1%, 0.1 W, 0603", Manufacturer="Susumu Co Ltd", Power_W=0.1, Supplier Part Number 1=RG16P49.9KBCT-ND, TempCo="25 ppm/C", Value1=0.1%, Value2=0.1W, Value_Code=49k9, ValueDisplayed=49.9k
R258 R261: "RES, 10.0 k, 0.1%, 0.1 W, 0603", Manufacturer="Susumu Co Ltd", Power_W=0.1, Supplier Part Number 1=RG16P10.0KBCT-ND, TempCo="25 ppm/C", Value1=0.1%, Value2=0.1W, Value_Code=10k0, ValueDisplayed=10.0k
R268 R269: "RES, 1.00, 1%, 0.1 W, 0603", Manufacturer=Vishay-Dale, Power_W=0.1, Supplier Part Number 1=71-CRCW06031R00FKEA, TempCo="100 ppm/C", Tolerance_%=1, Value1=1%, Value2=0.1W, Value_Code=1R00, ValueDisplayed=1.00
R290: "RES, 36 k, 5%, 0.063 W, 0402", Manufacturer=Vishay-Dale, Power_W=0.063, Supplier Part Number 1=541-36KJCT-ND, TempCo="200 ppm/C", Tolerance_%=5, Value1=5%, Value2=0.063W, Value_Code=36k0, ValueDisplayed=36k
R291 R295 R298: "RES, 100 k, 1%, 0.063 W, 0402", Manufacturer=Vishay-Dale, Power_W=0.063, Supplier Part Number 1=541-100KLCT-ND, TempCo="100 ppm/C", Tolerance_%=1, Value1=1%, Value2=0.063W, Value_Code=100k
R294: library part CMP-0016780-3, "RES, 20.5 k, 1%, 0.25 W, AEC-Q200 Grade 0, 1206", Manufacturer=Vishay-Dale, PartNumber=CRCW120620K5FKEA, Power_W=250mW, Supplier Part Number 1=541-20.5KFCT-ND, TempCo="100 ppm/C", Tolerance_%=1%, Value2=0.25W, Value_Code=20k5, ValueDisplayed=20.5k
R297: "RES, 5.62 k, 0.1%, 0.063 W, 0402", Manufacturer="TT Electronics/IRC", Power_W=0.063, TempCo="10 ppm/C", Tolerance_%=0.1, Value1=0.1%, Value2=0.063W, Value_Code=5k62, ValueDisplayed=5.62k
R401: "RES, 58.3 k, 0.1%, 0.1 W, 0603", Manufacturer="Yageo America", Power_W=0.1, TempCo="25 ppm/C", Value1=0.1%, Value2=0.1W, Value_Code=58k3, ValueDisplayed=58.3k
R402: "RES, 1.00 M, 1%, 0.1 W, 0603", Manufacturer="Yageo America", Power_W=0.1, Supplier Part Number 1=311-1.00MHRCT-ND, TempCo="200 ppm/C", Tolerance_%=1, Value1=1%, Value2=0.1W, Value_Code=1M00, ValueDisplayed=1.00M
R404: "RES, 80.6 k, 1%, 0.1 W, 0603", Manufacturer=Vishay-Dale, Power_W=0.1, Supplier Part Number 1=541-80.6KHCT-ND, TempCo="100 ppm/C", Tolerance_%=1, Value1=1%, Value2=0.1W, Value_Code=80k6, ValueDisplayed=80.6k
R486: "RES, 2.49 k, 0.1%, 0.1 W, 0603", Manufacturer="Susumu Co Ltd", Power_W=0.1, Supplier Part Number 1=RG16P2.49KBCT-ND, TempCo="25 ppm/C", Value1=0.1%, Value2=0.1W, Value_Code=2k49, ValueDisplayed=2.49k
R488: "RES, 4.99 k, 0.1%, 0.1 W, 0603", Manufacturer="Susumu Co Ltd", Power_W=0.1, Supplier Part Number 1=RG16P4.99KBCT-ND, TempCo="25 ppm/C", Value1=0.1%, Value2=0.1W, Value_Code=4k99, ValueDisplayed=4.99k
R489: "RES, 4.75, 1%, 0.1 W, 0603", Manufacturer=Vishay-Dale, Power_W=0.1, Supplier Part Number 1=541-4.75HHCT-ND, TempCo="100 ppm/C", Tolerance_%=1, Value1=1%, Value2=0.1W, Value_Code=4R75, ValueDisplayed=4.75
R494: "RES, 30.0 k, 0.1%, 0.1 W, 0603", Manufacturer="Susumu Co Ltd", Power_W=0.1, Supplier Part Number 1=RG16P30.0KBCT-ND, TempCo="25 ppm/C", Value1=0.1%, Value2=0.1W, Value_Code=30k0, ValueDisplayed=30.0k
RDN1 RDN3 RDP1 RDP3: "RES, 0, 5%, 0.1 W, 0603", Manufacturer=Panasonic, Power_W=0.1, Supplier Part Number 1=P0.0GCT-ND, TempCo="600 ppm/C", Tolerance_%=5, Value1=5%, Value2=0.1W, Value_Code=0000, ValueDisplayed=0
Renb: "RES, 20.5 k, 1%, 0.125 W, 0805", Manufacturer=Vishay-Dale, Power_W=0.125, Supplier Part Number 1=541-20.5KCCT-ND, TempCo="100 ppm/C", Tolerance_%=1, Value1=1%, Value2=0.125W, Value_Code=20k5, ValueDisplayed=20.5k
Renb2 Renb3: "RES, 3.57 k, 0.1%, 0.1 W, 0603", Manufacturer="Susumu Co Ltd", Power_W=0.1, Supplier Part Number 1=RG16P3.57KBCT-ND, TempCo="25 ppm/C", Value1=0.1%, Value2=0.1W, Value_Code=3k57, ValueDisplayed=3.57k
Rent: "RES, 118k ohm, 0.1%, 0.125W, 0805", Manufacturer="Yageo America", Power_W=0.125, Supplier Part Number 1=9983007, TempCo="25 ppm/C", Tolerance_%=0.1, Value1=0.1%, Value2=0.125W, Value_Code=118k
Rent2 Rent3: "RES, 68.1 k, 0.1%, 0.1 W, 0603", Manufacturer="Yageo America", Power_W=0.1, TempCo="25 ppm/C", Value1=0.1%, Value2=0.1W, Value_Code=68k1, ValueDisplayed=68.1k
RES3V RES5V RES18V: "RES, 100 k, 0.1%, 0.1 W, 0603", Manufacturer="Susumu Co Ltd", Power_W=0.1, Supplier Part Number 1=RG16P100KBCT-ND, TempCo="25 ppm/C", Value1=0.1%, Value2=0.1W, Value_Code=100k
Rfbb: "RES, 1.50 k, 0.1%, 0.1 W, 0603", Manufacturer="Susumu Co Ltd", Power_W=0.1, Supplier Part Number 1=RG16P1.5KBCT-ND, TempCo="25 ppm/C", Value1=0.1%, Value2=0.1W, Value_Code=1k50, ValueDisplayed=1.50k
Rfbb3 Rfbb5: "RES, 1.07 k, 0.1%, 0.125 W, 0805", Manufacturer="Yageo America", Power_W=0.125, Supplier Part Number 1=9982876, TempCo="25 ppm/C", Tolerance_%=0.1, Value1=0.1%, Value2=0.125W, Value_Code=1k07, ValueDisplayed=1.07k
Rfbt: "RES, 34.0 k, 0.1%, 0.1 W, 0603", Manufacturer="Yageo America", Power_W=0.1, TempCo="25 ppm/C", Value1=0.1%, Value2=0.1W, Value_Code=34k0, ValueDisplayed=34.0k
Rfbt2: "RES, 6.34 k, 0.1%, 0.063 W, 0603", Manufacturer="TE Connectivity", Power_W=0.063, TempCo="25 ppm/C", Tolerance_%=0.1, Value1=0.1%, Value2=0.063W, Value_Code=6k34, ValueDisplayed=6.34k
Rfbt3: "RES, 4.02 k, 0.1%, 0.1 W, 0603", Manufacturer="Susumu Co Ltd", Power_W=0.1, Supplier Part Number 1=RG16P4.02KBCT-ND, TempCo="25 ppm/C", Value1=0.1%, Value2=0.1W, Value_Code=4k02, ValueDisplayed=4.02k
Ron: "RES, 383 k, 0.1%, 0.1 W, 0603", Manufacturer="Yageo America", Power_W=0.1, TempCo="25 ppm/C", Value1=0.1%, Value2=0.1W, Value_Code=383k
Ron2: "RES, 113 k, 0.1%, 0.1 W, 0603", Manufacturer="Yageo America", Power_W=0.1, TempCo="25 ppm/C", Value1=0.1%, Value2=0.1W, Value_Code=113k
Ron3: "RES, 78.7 k, 0.1%, 0.1 W, 0603", Manufacturer="Yageo America", Power_W=0.1, TempCo="25 ppm/C", Value1=0.1%, Value2=0.1W, Value_Code=78k7, ValueDisplayed=78.7k
RR413: "RES, 0.22, 1%, 0.1 W, 0603", Manufacturer=Panasonic, Power_W=0.1, Supplier Part Number 1=P.22AJCT-ND, TempCo="300 ppm/C", Tolerance_%=1, Value1=1%, Value2=0.1W, Value_Code=R220, ValueDisplayed=0.22
TP1 TP2 TP4 TP7 TP16 TP31 TP32 TP33 TP34 TP35 TPAGND TPGND TPPGOOD: library part PogoPad, "Pad for Pogo Pin Connector"
U1 U2: "High Bandwidth, High Precision, Low Noise and Distortion Amplifier with Ultra-Fast Transition time Low Power mode, DBV0006A", Alternate Manufacturer="Texas Instruments", Alternate PartNumber=OPA625IDBVT
U3: library part CMP-0076438-1, "High-Precision Voltage Reference with Integrated High-Bandwidth Buffer, DGK0008A (VSSOP-8)", Alternate Manufacturer="Texas Instruments", Alternate PartNumber=REF6050IDGKT
U3P8V U5P5V U18P5V: "3.5A Synchronous Buck Regulator for Automotive Applications, RNL0022A (VQFN-HR-22)", Alternate Manufacturer="Texas Instruments", Alternate PartNumber=LMS3635MQRNLTQ1
U4: "Precision, Low Noise, Low Iq Operational Amplifier, 2.2 to 5.5 V, -40 to 125 degC, 5-pin SOT23 (DBV0005A), Green (RoHS & no Sb/Br)", Alternate Manufacturer="Texas Instruments", Alternate PartNumber=Equivalent, Supplier Part Number 1=OPA376AIDBVR-ND, Total Supply Voltage(Max)(+5V is 5, +/-5V is 10)=5.5, Total Supply Voltage(Min)(+5V is 5, +/-5V is 10)=2.2
U5: "2A SIMPLE SWITCHERR Power Module with 42V Maximum Input, 7 pin TO-PMOD", Manufacturer="Texas Instruments", PackageTopMarking=NSUZXYTTE#*LMZ14202*TZ-ADJ, PowerWise=Y, Supplier Part Number 1=LMZ14202TZX-ADJ-ND
U6 U7 U8: "36-V, 1-A, 4.17-兪VRMS, RF LDO Voltage Regulator, RGW0020A", Alternate Manufacturer="Texas Instruments", Alternate PartNumber=TPS7A4700RGWT
U9: "SIMPLE SWITCHERR 75V, 0.5A Step-Down Switching Regulator, 16-pin TSSOP", Manufacturer="Texas Instruments", PackageTopMarking=NSUZXYTT*LM5574*MT, PowerWise=Y, Supplier Part Number 1=1325419
U10: "Low Noise Negative Bias Generator, 8-pin Mini SOIC, Pb-Free", Manufacturer="Texas Instruments", PackageTopMarking=ZXTT*F26A, PowerWise=N, Supplier Part Number 1=LM7705MM-ND
U11: "Single Output High PSRR LDO, 200 mA, Adjustable -1.18 to -33 V Output, -3 to -36 V Input, with Ultra-Low Noise, 8-pin MSOP (DGN), -55 to 125 degC, Green (RoHS & no Sb/Br)", Alternate Manufacturer="Texas Instruments", Alternate PartNumber=Equivalent, Supplier Part Number 1=296-29768-2-ND
U13 U14: "I2C BUS EEPROM (2-Wire), TSSOP-B8", Manufacturer=Rohm, Supplier Part Number 1=BR24G32FVT-3AG2CT-ND
U15: "Ultra-Low Jitter Programmable Oscillator with Internal EEPROM, SIA0008B", Alternate Manufacturer="Texas Instruments", Alternate PartNumber=LMK61E2-SIAT
U18 U31: "LOW-POWER SINGLE POSITIVE-EDGE-TRIGGERED D-TYPE FLIP-FLOP, DCK0005A", Alternate Manufacturer="Texas Instruments", Alternate PartNumber=SN74AUP1G80DCKT
U19 U32: "SINGLE SCHMITT-TRIGGER INVERTER GATE, DBV0005A", Alternate Manufacturer="Texas Instruments", Alternate PartNumber=SN74AHC1G04DBVT
U22: "1A SIMPLE SWITCHERR Power Module with 42V Maximum Input, 7 pin TO-PMOD", Manufacturer="Texas Instruments", PackageTopMarking=NSUZXYTTE#*LMZ14201*TZ-ADJ, PowerWise=Y, Supplier Part Number 1=LMZ14201TZX-ADJ-ND
U23: "3A SIMPLE SWITCHERR Power Module with 42V Maximum Input Voltage, 7-pin TO-PMOD, Pb-Free", Manufacturer="Texas Instruments", PackageTopMarking=NSUZXYTTE#*LMZ14203*TZ-ADJ, PowerWise=Y, Supplier Part Number 1=LMZ14203TZ-ADJTR-ND
U33: "Low Skew, 1-to-4 Multiplexed Differential/LVCMOS-to-LVCMOS/TTL Fanout Buffer, PW0016A", Alternate Manufacturer="Texas Instruments"
U401: "SIMPLE SWITCHER 3.5 V to 60 V 1 A Synchronous Step-Down Voltage Converter, PWP0016G (TSSOP-16)", Alternate Manufacturer="Texas Instruments", Alternate PartNumber=LM46001PWPT
U414: "Low-Noise, 900 kHz, RRIO, Precision Operational Amplifier, Zero-Drift Series, 2.2 to 5.5 V, -40 to 125 degC, 5-pin SOT23 (DBV0005A), Green (RoHS & no Sb/Br)", Alternate Manufacturer="Texas Instruments", Alternate PartNumber=Equivalent, Supplier Part Number 1=296-24619-2-ND, Total Supply Voltage(Max)(+5V is 5, +/-5V is 10)=5.5, Total Supply Voltage(Min)(+5V is 5, +/-5V is 10)=2.2
U415: "High-Bandwidth, High-Precision, Low THD+N, 16-Bit and 18-Bit Analog-to-Digital Converter (ADC) Drivers, DBV0006A", Alternate Manufacturer="Texas Instruments", Alternate PartNumber=OPA625IDBVT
